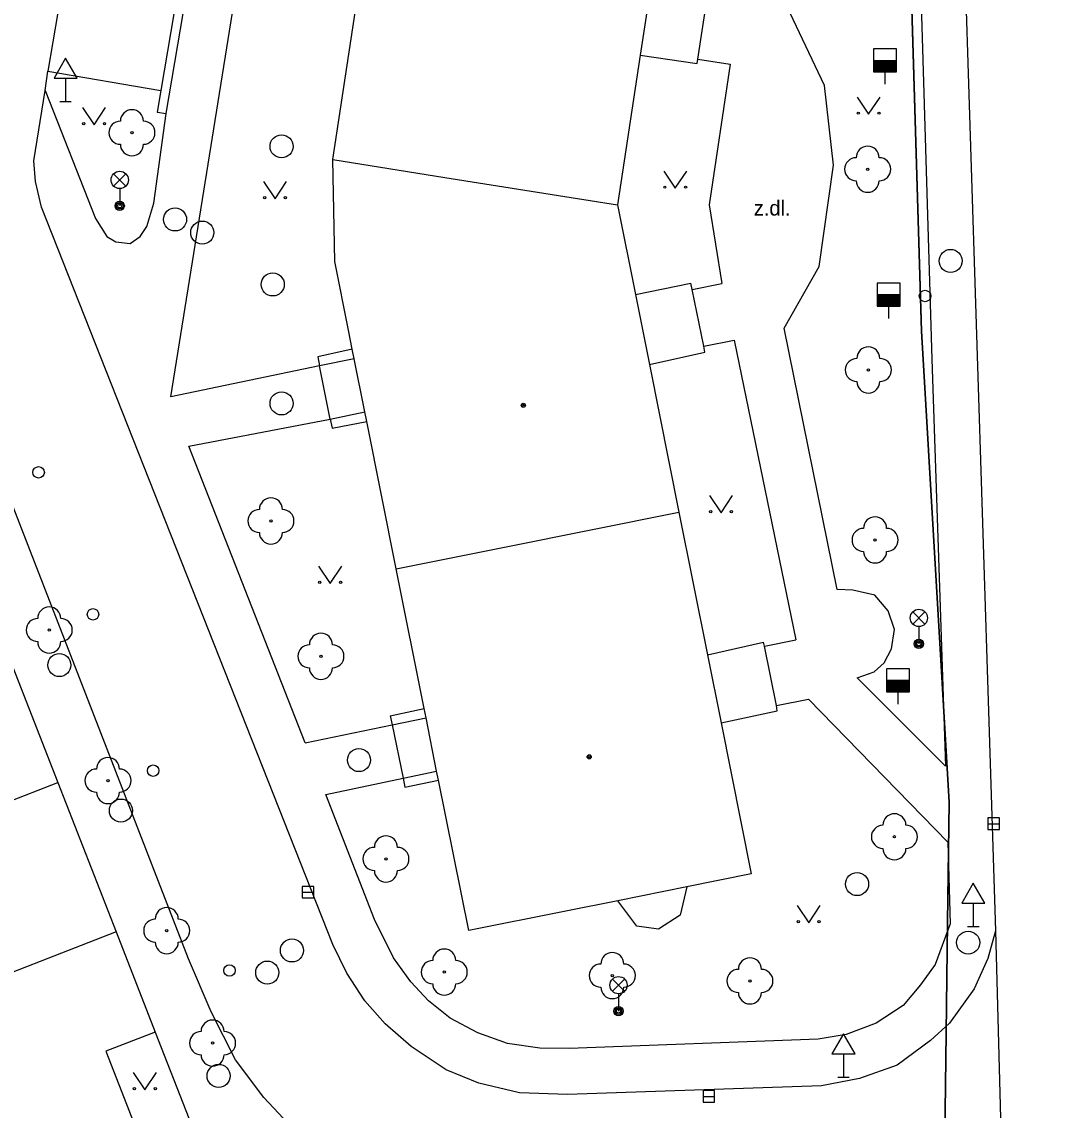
# Model space of a CAD drawing. Extents: x -598233 to -596890, y -1157848 to -1156431.
# Drawn here: x -598065.98 to -598021.45, y -1157032.43 to -1156985.21 of the extents above; entities that cross this region are included whole.
import ezdxf

# ---------------------------------------------------------------- set-up
doc = ezdxf.new("R2010")
doc.units = 0
for name, color, linetype in [('Level 10', 7, 'Continuous'), ('Level 11', 7, 'Continuous'), ('Level 22', 7, 'Continuous'), ('Level 27', 7, 'Continuous'), ('Level 28', 7, 'Continuous'), ('Level 33', 7, 'Continuous'), ('Level 34', 7, 'Continuous'), ('Level 36', 7, 'Continuous'), ('Level 39', 7, 'Continuous'), ('Level 40', 7, 'Continuous'), ('Level 5', 7, 'Continuous'), ('Level 7', 7, 'Continuous'), ('Vrstva 54', 7, 'Continuous'), ('Vrstva 60', 7, 'Continuous')]:
    doc.layers.add(name, color=color, linetype=linetype)

msp = doc.modelspace()

# ---------------------------------------------------------------- linework, layer by layer
at = {"layer": 'Level 10'}
for points in [[(-598058.75, -1157025.86), (-598073.33, -1156988.32), (-598077.41, -1156977.93), (-598095.18, -1156932.61)], [(-598061.59, -1156968.25), (-598064.85, -1156987.36)], [(-598025.11, -1156981.54), (-598023.74, -1157024.65)], [(-598064.9699, -1156988.2), (-598064.85, -1156987.36)], [(-598065.46, -1156991.25), (-598064.9699, -1156988.2)], [(-598065.38, -1156992.14), (-598065.46, -1156991.25)], [(-598065.12, -1156993.25), (-598065.38, -1156992.14)], [(-598052.49, -1157025.24), (-598065.12, -1156993.25)], [(-598023.74, -1157024.65), (-598024.06, -1157025.85), (-598024.6599, -1157027.17), (-598025.73, -1157028.6599), (-598026.56, -1157029.4099), (-598028, -1157030.4699)], [(-598023.74, -1157024.65), (-598024.06, -1157025.85), (-598024.6599, -1157027.17), (-598025.73, -1157028.6599), (-598026.56, -1157029.4099), (-598028, -1157030.4699)], [(-598050.2199, -1157028.68), (-598051.09, -1157027.68), (-598051.88, -1157026.48), (-598052.49, -1157025.24)], [(-598056.7, -1157030.25), (-598057.77, -1157028.1599), (-598058.75, -1157025.86)], [(-598046.15, -1157031.25), (-598047.57, -1157030.68), (-598049.09, -1157029.6599), (-598050.2199, -1157028.68)], [(-598054.2, -1157033.24), (-598055.48, -1157031.88), (-598056.7, -1157030.25)], [(-598028, -1157030.4699), (-598029.64, -1157031.05), (-598031.28, -1157031.37)], [(-598042.31, -1157031.75), (-598044.39, -1157031.68), (-598046.15, -1157031.25)], [(-598031.28, -1157031.37), (-598042.31, -1157031.75)]]:
    msp.add_lwpolyline(points, dxfattribs=at)
at = {"layer": 'Level 11'}
for points in [[(-598027.04, -1156981.57), (-598026.49, -1156999.85), (-598025.9, -1157017.5)], [(-598027.04, -1156981.57), (-598026.49, -1156999.85), (-598025.9, -1157017.5)], [(-598059.51, -1157001.49), (-598056.65, -1156983.63)], [(-598036.65, -1156986.83), (-598036.24, -1156984.17)], [(-598031.15, -1156987.98), (-598032.65, -1156984.84)], [(-598039.15, -1156986.67), (-598036.68, -1156987.02)], [(-598036.68, -1156987.02), (-598036.65, -1156986.83)], [(-598036.65, -1156986.83), (-598035.24, -1156987.05)], [(-598064.85, -1156987.36), (-598059.94, -1156988.19)], [(-598035.24, -1156987.05), (-598036.1599, -1156993.1599)], [(-598030.77, -1156991.44), (-598031.15, -1156987.98)], [(-598064.9699, -1156988.2), (-598062.78, -1156993.75)], [(-598060.25, -1156993.09), (-598059.71, -1156989.2)], [(-598031.39, -1156995.83), (-598030.77, -1156991.44)], [(-598060.55, -1156994.09), (-598060.25, -1156993.09)], [(-598036.1599, -1156993.1599), (-598035.61, -1156996.57)], [(-598062.78, -1156993.75), (-598062.29, -1156994.53)], [(-598061.27, -1156994.83), (-598060.84, -1156994.53), (-598060.55, -1156994.09)], [(-598062.29, -1156994.53), (-598061.9, -1156994.76), (-598061.27, -1156994.83)], [(-598032.9, -1156998.51), (-598031.39, -1156995.83)], [(-598039.36, -1156997.05), (-598036.95, -1156996.56)], [(-598036.89, -1156996.83), (-598036.95, -1156996.56)], [(-598036.89, -1156996.83), (-598035.61, -1156996.57)], [(-598036.39, -1156999.29), (-598036.89, -1156996.83)], [(-598030.6, -1157009.84), (-598032.9, -1156998.51)], [(-598036.39, -1156999.29), (-598035.07, -1156999.02)], [(-598036.34, -1156999.55), (-598036.39, -1156999.29)], [(-598035.07, -1156999.02), (-598032.4, -1157012.03)], [(-598051.64, -1156999.42), (-598053.14, -1156999.75)], [(-598053.14, -1156999.75), (-598053.06, -1157000.14)], [(-598038.75, -1157000.08), (-598036.34, -1156999.55)], [(-598053.06, -1157000.14), (-598059.51, -1157001.49)], [(-598051.56, -1156999.84), (-598053.06, -1157000.14)], [(-598052.6, -1157002.45), (-598053.06, -1157000.14)], [(-598052.6, -1157002.45), (-598051.09, -1157002.14)], [(-598058.73, -1157003.63), (-598052.6, -1157002.45)], [(-598052.6, -1157002.45), (-598052.52, -1157002.84)], [(-598052.52, -1157002.84), (-598051.01, -1157002.56)], [(-598053.69, -1157016.5), (-598058.73, -1157003.63)], [(-598028.9699, -1157010.09), (-598029.93, -1157009.87), (-598030.6, -1157009.84)], [(-598028.11, -1157011.58), (-598028.39, -1157010.77), (-598028.9699, -1157010.09)], [(-598028.56, -1157013.03), (-598028.25, -1157012.4099), (-598028.11, -1157011.58)], [(-598033.76, -1157012.3), (-598032.4, -1157012.03)], [(-598036.23, -1157012.67), (-598033.8, -1157012.12)], [(-598033.76, -1157012.3), (-598033.8, -1157012.12)], [(-598033.24, -1157014.88), (-598033.76, -1157012.3)], [(-598029.73, -1157013.67), (-598029, -1157013.4099), (-598028.56, -1157013.03)], [(-598025.9, -1157017.5), (-598029.73, -1157013.67)], [(-598033.24, -1157014.88), (-598031.85, -1157014.6)], [(-598033.2, -1157015.1), (-598033.24, -1157014.88)], [(-598031.85, -1157014.6), (-598025.8, -1157020.8)], [(-598049.99, -1157015.32), (-598048.52, -1157015.01)], [(-598049.99, -1157015.32), (-598049.9099, -1157015.71)], [(-598035.64, -1157015.62), (-598033.2, -1157015.1)], [(-598053.69, -1157016.5), (-598049.9099, -1157015.71)], [(-598049.9099, -1157015.71), (-598048.44, -1157015.4099)], [(-598049.9099, -1157015.71), (-598049.44, -1157018.02)], [(-598049.44, -1157018.02), (-598047.98, -1157017.7199)], [(-598052.79, -1157018.73), (-598049.44, -1157018.02)], [(-598049.44, -1157018.02), (-598049.36, -1157018.4099)], [(-598049.36, -1157018.4099), (-598047.9, -1157018.11)], [(-598050.68, -1157024.15), (-598052.79, -1157018.73)], [(-598025.8, -1157020.8), (-598025.7, -1157024.35), (-598026.35, -1157026.11), (-598026.99, -1157026.99)], [(-598025.8, -1157020.8), (-598025.7, -1157024.35), (-598026.35, -1157026.11), (-598026.99, -1157026.99)], [(-598037.12, -1157022.74), (-598037.4099, -1157023.9699), (-598038.35, -1157024.58), (-598039.3, -1157024.44), (-598040.12, -1157023.34)], [(-598048.34, -1157027.69), (-598049.1, -1157026.86), (-598049.85, -1157025.82), (-598050.68, -1157024.15)], [(-598023.74, -1157024.65), (-598023.23, -1157043.6)], [(-598026.99, -1157026.99), (-598027.74, -1157027.88), (-598028.9099, -1157028.6599), (-598030.2199, -1157029.14)], [(-598046.19, -1157029.07), (-598047.39, -1157028.44), (-598048.34, -1157027.69)], [(-598060.19, -1157029.04), (-598058.73, -1157032.78)], [(-598042.23, -1157029.75), (-598043.51, -1157029.74), (-598044.9, -1157029.53), (-598046.19, -1157029.07)], [(-598031.43, -1157029.35), (-598042.23, -1157029.75)], [(-598030.2199, -1157029.14), (-598031.43, -1157029.35)]]:
    msp.add_lwpolyline(points, dxfattribs=at)
at = {"layer": 'Level 22'}
for centre in [(-598061.2, -1156990.03), (-598029.28, -1156991.61), (-598029.25, -1157000.32), (-598055.17, -1157006.87), (-598028.96, -1157007.69), (-598064.79, -1157011.6), (-598053, -1157012.74), (-598062.24, -1157018.13), (-598028.12, -1157020.57), (-598050.18, -1157021.53), (-598059.69, -1157024.64), (-598047.65, -1157026.44), (-598040.36, -1157026.59), (-598034.39, -1157026.82), (-598057.7, -1157029.52)]:
    msp.add_circle(centre, 0.05, dxfattribs=at)
for centre, start, end in [((-598061.2, -1156989.53), 0, 180), ((-598061.7, -1156990.03), 90, 270), ((-598060.7, -1156990.03), 270, 90), ((-598061.2, -1156990.53), 180, 0), ((-598029.28, -1156991.11), 0, 180), ((-598029.78, -1156991.61), 90, 270), ((-598028.78, -1156991.61), 270, 90), ((-598029.28, -1156992.11), 180, 0), ((-598029.25, -1156999.82), 0, 180), ((-598029.75, -1157000.32), 90, 270), ((-598028.75, -1157000.32), 270, 90), ((-598029.25, -1157000.82), 180, 0), ((-598055.17, -1157006.37), 0, 180), ((-598055.67, -1157006.87), 90, 270), ((-598054.67, -1157006.87), 270, 90), ((-598028.96, -1157007.19), 0, 180), ((-598029.46, -1157007.69), 90, 270), ((-598028.46, -1157007.69), 270, 90), ((-598055.17, -1157007.37), 180, 0), ((-598028.96, -1157008.19), 180, 0), ((-598064.79, -1157011.1), 0, 180), ((-598065.29, -1157011.6), 90, 270), ((-598064.29, -1157011.6), 270, 90), ((-598053, -1157012.24), 0, 180), ((-598064.79, -1157012.1), 180, 0), ((-598053.5, -1157012.74), 90, 270), ((-598052.5, -1157012.74), 270, 90), ((-598053, -1157013.24), 180, 0), ((-598062.24, -1157017.63), 0, 180), ((-598062.74, -1157018.13), 90, 270), ((-598061.74, -1157018.13), 270, 90), ((-598062.24, -1157018.63), 180, 0), ((-598028.12, -1157020.07), 0, 180), ((-598028.62, -1157020.57), 90, 270), ((-598027.62, -1157020.57), 270, 90), ((-598050.18, -1157021.03), 0, 180), ((-598050.68, -1157021.53), 90, 270), ((-598049.68, -1157021.53), 270, 90), ((-598028.12, -1157021.07), 180, 0), ((-598050.18, -1157022.03), 180, 0), ((-598059.69, -1157024.14), 0, 180), ((-598060.19, -1157024.64), 90, 270), ((-598059.19, -1157024.64), 270, 90), ((-598059.69, -1157025.14), 180, 0), ((-598047.65, -1157025.94), 0, 180), ((-598040.36, -1157026.09), 0, 180), ((-598048.15, -1157026.44), 90, 270), ((-598047.15, -1157026.44), 270, 90), ((-598040.86, -1157026.59), 90, 270), ((-598039.86, -1157026.59), 270, 90), ((-598034.39, -1157026.32), 0, 180), ((-598034.89, -1157026.82), 90, 270), ((-598033.89, -1157026.82), 270, 90), ((-598047.65, -1157026.94), 180, 0), ((-598040.36, -1157027.09), 180, 0), ((-598034.39, -1157027.32), 180, 0), ((-598057.7, -1157029.02), 0, 180), ((-598058.2, -1157029.52), 90, 270), ((-598057.2, -1157029.52), 270, 90), ((-598057.7, -1157030.02), 180, 0)]:
    msp.add_arc(centre, 0.5, start, end, dxfattribs=at)
at = {"layer": 'Level 27'}
for p, q in [((-598024.06, -1157020), (-598023.56, -1157020)), ((-598053.81, -1157022.9699), (-598053.31, -1157022.9699)), ((-598036.42, -1157031.83), (-598035.92, -1157031.83))]:
    msp.add_line(p, q, dxfattribs=at)
for points in [[(-598024.06, -1157020.25), (-598023.56, -1157020.25), (-598023.56, -1157019.75), (-598024.06, -1157019.75)], [(-598053.81, -1157023.2199), (-598053.31, -1157023.2199), (-598053.31, -1157022.7199), (-598053.81, -1157022.7199)], [(-598036.42, -1157032.08), (-598035.92, -1157032.08), (-598035.92, -1157031.58), (-598036.42, -1157031.58)]]:
    msp.add_lwpolyline(points, close=True, dxfattribs=at)
for centre in [(-598054.71, -1156990.62), (-598059.33, -1156993.79), (-598058.15, -1156994.36), (-598025.68, -1156995.59), (-598055.09, -1156996.61), (-598054.71, -1157001.77), (-598064.35, -1157013.12), (-598051.35, -1157017.24), (-598061.68, -1157019.43), (-598029.74, -1157022.62), (-598024.92, -1157025.1599), (-598054.26, -1157025.5), (-598055.33, -1157026.46), (-598057.44, -1157030.94)]:
    msp.add_circle(centre, 0.5, dxfattribs=at)
at = {"layer": 'Level 28'}
for p, q in [((-598029.03, -1156986.89), (-598028.03, -1156986.89)), ((-598029.03, -1156986.94), (-598028.03, -1156986.94)), ((-598029.03, -1156986.99), (-598028.03, -1156986.99)), ((-598029.03, -1156987.04), (-598028.03, -1156987.04)), ((-598029.03, -1156987.09), (-598028.03, -1156987.09)), ((-598029.03, -1156987.14), (-598028.03, -1156987.14)), ((-598029.03, -1156987.19), (-598028.03, -1156987.19)), ((-598029.03, -1156987.24), (-598028.03, -1156987.24)), ((-598029.03, -1156987.29), (-598028.03, -1156987.29)), ((-598029.03, -1156987.34), (-598028.03, -1156987.34)), ((-598028.53, -1156987.39), (-598028.53, -1156987.92)), ((-598028.87, -1156997.05), (-598027.87, -1156997.05)), ((-598028.87, -1156997.1), (-598027.87, -1156997.1)), ((-598028.87, -1156997.15), (-598027.87, -1156997.15)), ((-598028.87, -1156997.2), (-598027.87, -1156997.2)), ((-598028.87, -1156997.25), (-598027.87, -1156997.25)), ((-598028.87, -1156997.3), (-598027.87, -1156997.3)), ((-598028.87, -1156997.35), (-598027.87, -1156997.35)), ((-598028.87, -1156997.4), (-598027.87, -1156997.4)), ((-598028.87, -1156997.45), (-598027.87, -1156997.45)), ((-598028.87, -1156997.5), (-598027.87, -1156997.5)), ((-598028.37, -1156997.55), (-598028.37, -1156998.08)), ((-598028.4699, -1157013.78), (-598027.4699, -1157013.78)), ((-598028.4699, -1157013.83), (-598027.4699, -1157013.83)), ((-598028.4699, -1157013.88), (-598027.4699, -1157013.88)), ((-598028.4699, -1157013.93), (-598027.4699, -1157013.93)), ((-598028.4699, -1157013.98), (-598027.4699, -1157013.98)), ((-598028.4699, -1157014.03), (-598027.4699, -1157014.03)), ((-598028.4699, -1157014.08), (-598027.4699, -1157014.08)), ((-598028.4699, -1157014.13), (-598027.4699, -1157014.13)), ((-598028.4699, -1157014.18), (-598027.4699, -1157014.18)), ((-598028.4699, -1157014.23), (-598027.4699, -1157014.23)), ((-598027.9699, -1157014.28), (-598027.9699, -1157014.81))]:
    msp.add_line(p, q, dxfattribs=at)
for points in [[(-598029.03, -1156987.39), (-598028.03, -1156987.39), (-598028.03, -1156986.39), (-598029.03, -1156986.39)], [(-598028.87, -1156997.55), (-598027.87, -1156997.55), (-598027.87, -1156996.55), (-598028.87, -1156996.55)], [(-598028.4699, -1157014.28), (-598027.4699, -1157014.28), (-598027.4699, -1157013.28), (-598028.4699, -1157013.28)]]:
    msp.add_lwpolyline(points, close=True, dxfattribs=at)
for centre in [(-598026.79, -1156997.11), (-598065.25, -1157004.76), (-598062.89, -1157010.92), (-598060.28, -1157017.7), (-598056.9699, -1157026.37)]:
    msp.add_circle(centre, 0.25, dxfattribs=at)
at = {"layer": 'Level 33'}
for p, q in [((-598061.995, -1156992.34), (-598061.465, -1156991.81)), ((-598061.995, -1156991.81), (-598061.465, -1156992.34)), ((-598061.73, -1156992.45), (-598061.73, -1156993.2)), ((-598027.325, -1157011.34), (-598026.795, -1157010.81)), ((-598027.325, -1157010.81), (-598026.795, -1157011.34)), ((-598027.06, -1157011.45), (-598027.06, -1157012.2)), ((-598040.355, -1157027.27), (-598039.825, -1157026.74)), ((-598040.355, -1157026.74), (-598039.825, -1157027.27)), ((-598040.09, -1157027.38), (-598040.09, -1157028.13))]:
    msp.add_line(p, q, dxfattribs=at)
for centre, radius in [((-598061.73, -1156992.075), 0.375), ((-598061.73, -1156993.2), 0.2), ((-598061.73, -1156993.2), 0.1445), ((-598061.73, -1156993.2), 0.0876), ((-598027.06, -1157011.075), 0.375), ((-598027.06, -1157012.2), 0.2), ((-598027.06, -1157012.2), 0.1445), ((-598027.06, -1157012.2), 0.0876), ((-598040.09, -1157027.005), 0.375), ((-598040.09, -1157028.13), 0.2), ((-598040.09, -1157028.13), 0.1445), ((-598040.09, -1157028.13), 0.0876)]:
    msp.add_circle(centre, radius, dxfattribs=at)
at = {"layer": 'Level 34'}
for p, q in [((-598064.08, -1156987.662), (-598064.08, -1156988.68)), ((-598064.33, -1156988.68), (-598063.83, -1156988.68)), ((-598024.7, -1157023.442), (-598024.7, -1157024.46)), ((-598024.95, -1157024.46), (-598024.45, -1157024.46)), ((-598030.33, -1157029.982), (-598030.33, -1157031)), ((-598030.58, -1157031), (-598030.08, -1157031))]:
    msp.add_line(p, q, dxfattribs=at)
for points in [[(-598064.58, -1156987.662), (-598063.58, -1156987.662), (-598064.08, -1156986.796)], [(-598025.2, -1157023.442), (-598024.2, -1157023.442), (-598024.7, -1157022.576)], [(-598030.83, -1157029.982), (-598029.83, -1157029.982), (-598030.33, -1157029.116)]]:
    msp.add_lwpolyline(points, close=True, dxfattribs=at)
at = {"layer": 'Level 36'}
for points in [[(-598029.74, -1156988.48), (-598029.24, -1156989.23), (-598028.74, -1156988.48)], [(-598063.34, -1156988.94), (-598062.84, -1156989.69), (-598062.34, -1156988.94)], [(-598038.13, -1156991.69), (-598037.63, -1156992.44), (-598037.13, -1156991.69)], [(-598055.49, -1156992.14), (-598054.99, -1156992.89), (-598054.49, -1156992.14)], [(-598036.14, -1157005.77), (-598035.64, -1157006.52), (-598035.14, -1157005.77)], [(-598053.1, -1157008.83), (-598052.6, -1157009.58), (-598052.1, -1157008.83)], [(-598032.34, -1157023.55), (-598031.84, -1157024.3), (-598031.34, -1157023.55)], [(-598061.14, -1157030.8), (-598060.64, -1157031.55), (-598060.14, -1157030.8)]]:
    msp.add_lwpolyline(points, dxfattribs=at)
for centre in [(-598029.6902, -1156989.1798), (-598028.7908, -1156989.1798), (-598063.2902, -1156989.6398), (-598062.3908, -1156989.6398), (-598038.0802, -1156992.3898), (-598037.1808, -1156992.3898), (-598055.4402, -1156992.8398), (-598054.5408, -1156992.8398), (-598036.0902, -1157006.4698), (-598035.1908, -1157006.4698), (-598053.0502, -1157009.5298), (-598052.1508, -1157009.5298), (-598032.2902, -1157024.2498), (-598031.3908, -1157024.2498), (-598061.0902, -1157031.4998), (-598060.1908, -1157031.4998)]:
    msp.add_circle(centre, 0.05, dxfattribs=at)
at = {"layer": 'Level 39'}
for centre, radius in [((-598044.2199, -1157001.85), 0.09), ((-598044.2199, -1157001.85), 0.0398), ((-598041.36, -1157017.1), 0.09), ((-598041.36, -1157017.1), 0.0398)]:
    msp.add_circle(centre, radius, dxfattribs=at)
at = {"layer": 'Level 5'}
for points in [[(-598038.69, -1156983.64), (-598039.15, -1156986.67)], [(-598052.49, -1156991.19), (-598051.52, -1156984.82)], [(-598039.15, -1156986.67), (-598040.14, -1156993.1599)], [(-598052.49, -1156991.19), (-598047.63, -1156991.9699)], [(-598052.4, -1156995.61), (-598052.49, -1156991.19)], [(-598047.63, -1156991.9699), (-598040.14, -1156993.1599)], [(-598040.14, -1156993.1599), (-598039.36, -1156997.05)], [(-598051.8, -1156998.59), (-598052.4, -1156995.61)], [(-598039.36, -1156997.05), (-598038.75, -1157000.08)], [(-598051.64, -1156999.42), (-598051.8, -1156998.59)], [(-598051.56, -1156999.84), (-598051.64, -1156999.42)], [(-598051.09, -1157002.14), (-598051.56, -1156999.84)], [(-598038.75, -1157000.08), (-598037.4699, -1157006.49)], [(-598051.01, -1157002.56), (-598051.09, -1157002.14)], [(-598049.73, -1157008.95), (-598051.01, -1157002.56)], [(-598045.03, -1157008.01), (-598037.4699, -1157006.49)], [(-598037.4699, -1157006.49), (-598036.23, -1157012.67)], [(-598049.73, -1157008.95), (-598045.03, -1157008.01)], [(-598048.52, -1157015.01), (-598049.73, -1157008.95)], [(-598066.94, -1157011.76), (-598064.42, -1157018.21)], [(-598036.23, -1157012.67), (-598035.64, -1157015.62)], [(-598048.44, -1157015.4099), (-598048.52, -1157015.01)], [(-598047.98, -1157017.7199), (-598048.44, -1157015.4099)], [(-598035.64, -1157015.62), (-598034.33, -1157022.18)], [(-598047.9, -1157018.11), (-598047.98, -1157017.7199)], [(-598071.33, -1157020.9), (-598064.42, -1157018.21)], [(-598064.42, -1157018.21), (-598061.89, -1157024.69)], [(-598046.59, -1157024.64), (-598047.9, -1157018.11)], [(-598034.33, -1157022.18), (-598037.12, -1157022.74)], [(-598037.12, -1157022.74), (-598040.12, -1157023.34)], [(-598040.12, -1157023.34), (-598042.37, -1157023.79)], [(-598042.37, -1157023.79), (-598046.59, -1157024.64)], [(-598061.89, -1157024.69), (-598069.08, -1157027.5)], [(-598061.89, -1157024.69), (-598060.19, -1157029.04)], [(-598060.19, -1157029.04), (-598062.33, -1157029.87)], [(-598062.33, -1157029.87), (-598060.87, -1157033.62)]]:
    msp.add_lwpolyline(points, dxfattribs=at)
at = {"layer": 'Level 7'}
for points in [[(-598057.21, -1156966.42), (-598056.63, -1156967.81), (-598056.6, -1156968.48), (-598059.94, -1156988.19)], [(-598059.71, -1156989.2), (-598056.2, -1156968.51)], [(-598059.94, -1156988.19), (-598060.1, -1156989.13), (-598059.71, -1156989.2)]]:
    msp.add_lwpolyline(points, dxfattribs=at)
at = {"layer": 'Vrstva 54'}
for p, q in [((-598027.67, -1156974.53), (-598026.95, -1156998.63)), ((-598026.95, -1156998.63), (-598025.75, -1157019.06)), ((-598025.75, -1157019.06), (-598025.81, -1157024.28)), ((-598025.81, -1157024.28), (-598025.87, -1157029.09)), ((-598025.87, -1157029.09), (-598026, -1157039.23))]:
    msp.add_line(p, q, dxfattribs=at)
at = {"layer": 'Vrstva 60'}
for points in [[(-598027.67, -1156974.53), (-598026.95, -1156998.63), (-598025.75, -1157019.06), (-598025.81, -1157024.28), (-598025.87, -1157029.09), (-598026, -1157039.23), (-598025.69, -1157044.06), (-598024.89, -1157056.73), (-598024.97, -1157072.7), (-598025, -1157077.78), (-598022.29, -1157077.5), (-598016.22, -1157076.88)], [(-598016.22, -1157076.88), (-598022.29, -1157077.5), (-598025, -1157077.78), (-598024.97, -1157072.7), (-598024.89, -1157056.73), (-598025.69, -1157044.06), (-598026, -1157039.23), (-598025.87, -1157029.09), (-598025.81, -1157024.28), (-598025.75, -1157019.06), (-598026.95, -1156998.63), (-598027.67, -1156974.53)]]:
    msp.add_lwpolyline(points, dxfattribs=at)

# ---------------------------------------------------------------- texts
at = {"layer": 'Level 40'}
msp.add_text('z.dl.', height=0.65, dxfattribs=at).set_placement((-598034.2199, -1156993.62))

doc.saveas('drawing.dxf')
